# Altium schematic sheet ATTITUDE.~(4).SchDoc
size A4
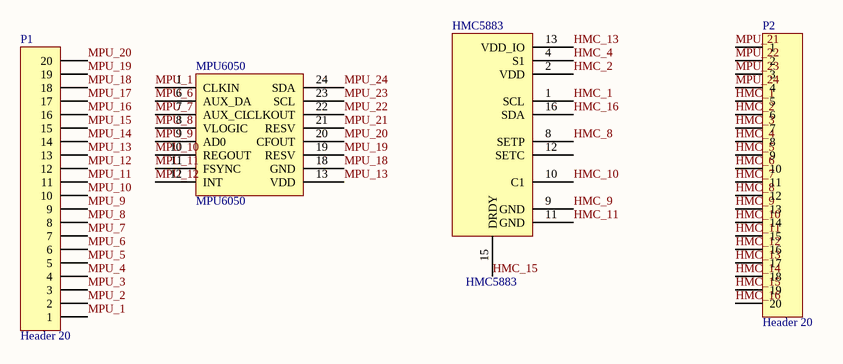
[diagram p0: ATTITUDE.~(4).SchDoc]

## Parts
HMC5883  HMC5883  [HMC5883]
MPU6050  MPU6050  [MPU6050]
P1  Header 20  [HDR1X20]
P2  Header 20  [HDR1X20]

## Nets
HMC_1: HMC5883.1(SCL) P2.5
HMC_2: HMC5883.2(VDD) P2.6
HMC_3: P2.7
HMC_4: HMC5883.4(S1) P2.8
HMC_5: P2.9
HMC_6: P2.10
HMC_7: P2.11
HMC_8: HMC5883.8(SETP) P2.12
HMC_9: HMC5883.9(GND) P2.13
HMC_10: HMC5883.10(C1) P2.14
HMC_11: HMC5883.11(GND) P2.15
HMC_12: P2.16
HMC_13: HMC5883.13(VDD_IO) P2.17
HMC_14: P2.18
HMC_15: HMC5883.15(DRDY) P2.19
HMC_16: HMC5883.16(SDA) P2.20
MPU_1: MPU6050.1(CLKIN) P1.1
MPU_2: P1.2
MPU_3: P1.3
MPU_4: P1.4
MPU_5: P1.5
MPU_6: MPU6050.6(AUX_DA) P1.6
MPU_7: MPU6050.7(AUX_CL) P1.7
MPU_8: MPU6050.8(VLOGIC) P1.8
MPU_9: MPU6050.9(AD0) P1.9
MPU_10: MPU6050.10(REGOUT) P1.10
MPU_11: MPU6050.11(FSYNC) P1.11
MPU_12: MPU6050.12(INT) P1.12
MPU_13: MPU6050.13(VDD) P1.13
MPU_14: P1.14
MPU_15: P1.15
MPU_16: P1.16
MPU_17: P1.17
MPU_18: MPU6050.18(GND) P1.18
MPU_19: MPU6050.19(RESV) P1.19
MPU_20: MPU6050.20(CFOUT) P1.20
MPU_21: MPU6050.21(RESV) P2.1
MPU_22: MPU6050.22(CLKOUT) P2.2
MPU_23: MPU6050.23(SCL) P2.3
MPU_24: MPU6050.24(SDA) P2.4

Not connected (* = marked no-connect by the designer): HMC5883 12(SETC)

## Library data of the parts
HMC5883 MPU6050 = Component_1
P1 P2 = Header 20: Header, 20-Pin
